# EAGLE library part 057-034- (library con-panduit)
CONNECTOR 34-pin series 057 contact pc board low profile headers
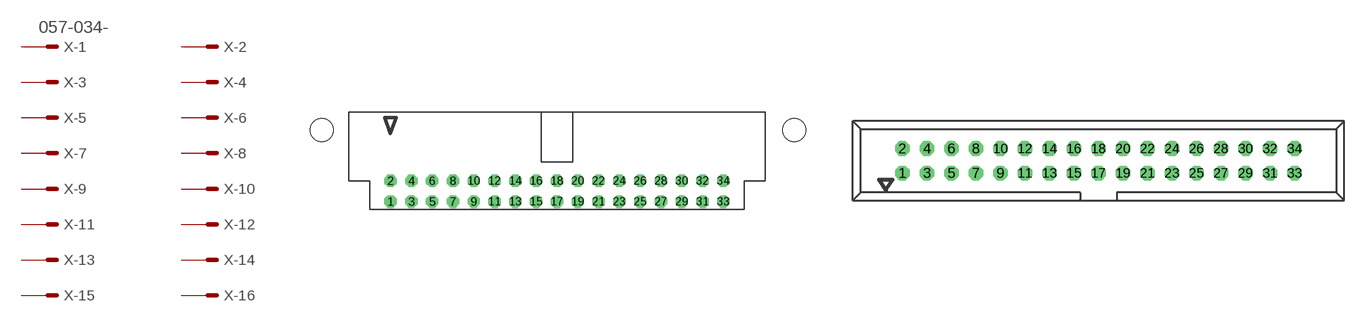
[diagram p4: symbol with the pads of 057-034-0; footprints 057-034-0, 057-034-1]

Designator prefix X; gates -1=MV -2=M -3=M -4=M -5=M -6=M -7=M -8=M -9=M -10=M -11=M -12=M -13=M -14=M -15=M -16=M -17=M -18=M -19=M -20=M -21=M -22=M -23=M -24=M -25=M -26=M -27=M -28=M -29=M -30=M -31=M -32=M -33=M -34=M

## 057-034-0 (OC_FARNELL: unknown; OC_NEWARK: unknown)  [057-034-0]
1  -1:S  pas
2  -2:S  pas
3  -3:S  pas
4  -4:S  pas
5  -5:S  pas
6  -6:S  pas
7  -7:S  pas
8  -8:S  pas
9  -9:S  pas
10  -10:S  pas
11  -11:S  pas
12  -12:S  pas
13  -13:S  pas
14  -14:S  pas
15  -15:S  pas
16  -16:S  pas
17  -17:S  pas
18  -18:S  pas
19  -19:S  pas
20  -20:S  pas
21  -21:S  pas
22  -22:S  pas
23  -23:S  pas
24  -24:S  pas
25  -25:S  pas
26  -26:S  pas
27  -27:S  pas
28  -28:S  pas
29  -29:S  pas
30  -30:S  pas
31  -31:S  pas
32  -32:S  pas
33  -33:S  pas
34  -34:S  pas

## 057-034-1 (OC_FARNELL: unknown; OC_NEWARK: unknown)  [057-034-1]
Pads as for 057-034-0

## Footprint 057-034-0 (pad centres in mm)
CONNECTOR series 057 contact pc board low profile headers angled
drill 1 octagon: 1 -20.32,-5.08; 2 -20.32,-2.54; 3 -17.78,-5.08; 4 -17.78,-2.54; 5 -15.24,-5.08; 6 -15.24,-2.54; 7 -12.7,-5.08; 8 -12.7,-2.54; 9 -10.16,-5.08; 10 -10.16,-2.54; 11 -7.62,-5.08; 12 -7.62,-2.54; 13 -5.08,-5.08; 14 -5.08,-2.54; 15 -2.54,-5.08; 16 -2.54,-2.54; 17 0,-5.08; 18 0,-2.54; 19 2.54,-5.08; 20 2.54,-2.54; 21 5.08,-5.08; 22 5.08,-2.54; 23 7.62,-5.08; 24 7.62,-2.54; 25 10.16,-5.08; 26 10.16,-2.54; 27 12.7,-5.08; 28 12.7,-2.54; 29 15.24,-5.08; 30 15.24,-2.54; 31 17.78,-5.08; 32 17.78,-2.54; 33 20.32,-5.08; 34 20.32,-2.54
hole 2.8 at -28.72,3.66
hole 2.8 at 28.97,3.66

## Footprint 057-034-1 (pad centres in mm)
CONNECTOR series 057 contact pc board low profile headers straight
drill 1 octagon: 1 -20.32,-1.27; 2 -20.32,1.27; 3 -17.78,-1.27; 4 -17.78,1.27; 5 -15.24,-1.27; 6 -15.24,1.27; 7 -12.7,-1.27; 8 -12.7,1.27; 9 -10.16,-1.27; 10 -10.16,1.27; 11 -7.62,-1.27; 12 -7.62,1.27; 13 -5.08,-1.27; 14 -5.08,1.27; 15 -2.54,-1.27; 16 -2.54,1.27; 17 0,-1.27; 18 0,1.27; 19 2.54,-1.27; 20 2.54,1.27; 21 5.08,-1.27; 22 5.08,1.27; 23 7.62,-1.27; 24 7.62,1.27; 25 10.16,-1.27; 26 10.16,1.27; 27 12.7,-1.27; 28 12.7,1.27; 29 15.24,-1.27; 30 15.24,1.27; 31 17.78,-1.27; 32 17.78,1.27; 33 20.32,-1.27; 34 20.32,1.27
